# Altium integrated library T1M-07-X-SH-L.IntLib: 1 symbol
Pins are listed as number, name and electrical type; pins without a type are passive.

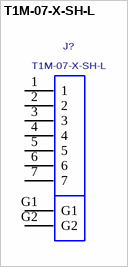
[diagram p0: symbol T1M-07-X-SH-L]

## T1M-07-X-SH-L
designator J?
1 MM SINGLE ROW DISCRETE WIRE HEADER, 7 PINS.; MANUFACTURER: SAMTEC
footprint T1M-07-X-SH-L
pins: 1, 2, 3, 4, 5, 6, 7, G1, G2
